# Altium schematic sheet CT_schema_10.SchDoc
size 274 x 160 mm
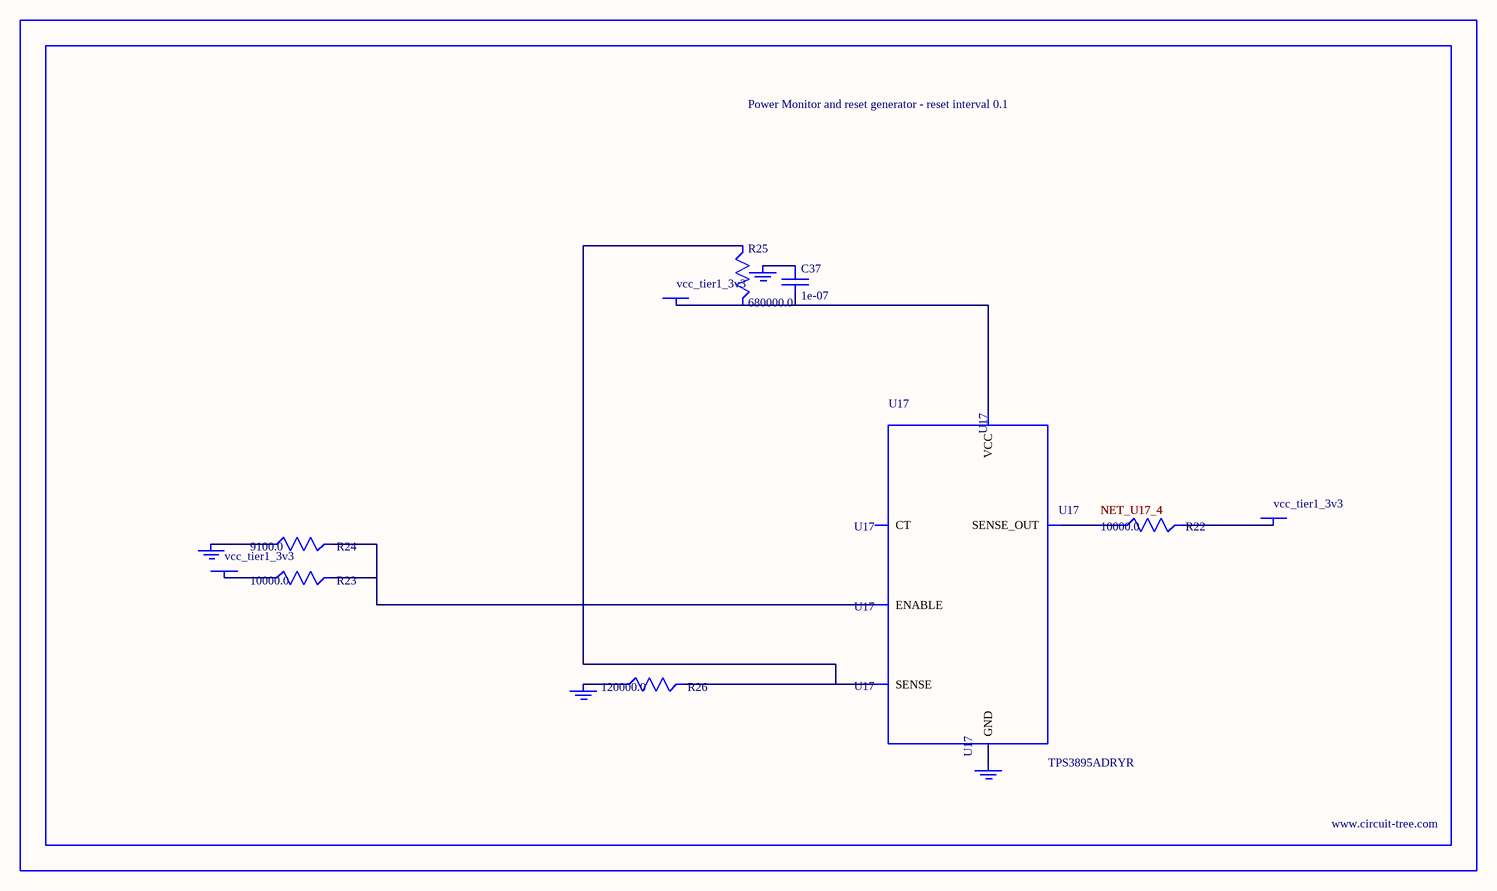
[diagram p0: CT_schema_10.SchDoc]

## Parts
BORDER9  (no value)
C37  1e-07  [C0402]
GND_INSTANCE_9_0  (no value)
GND_INSTANCE_9_1  (no value)
GND_INSTANCE_9_2  (no value)
GND_INSTANCE_9_3  (no value)
POWER_INSTANCE_9_0  vcc_tier1_3v3
POWER_INSTANCE_9_1  vcc_tier1_3v3
POWER_INSTANCE_9_2  vcc_tier1_3v3
R22  10000.0  [R0603]
R23  10000.0  [R0603]
R24  9100.0  [R0603]
R25  680000.0  [R0603]
R26  120000.0  [R0603]
U17  TPS3895ADRYR  [SON-6]

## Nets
NetC37_1: C37.1 GND_INSTANCE_9_2.0(GND)
NetC37_2: C37.2 POWER_INSTANCE_9_2.0(PWR) R25.2 U17.6(VCC)
NetGND_INSTANCE_9_0_0: GND_INSTANCE_9_0.0(GND) R24.1
NetGND_INSTANCE_9_1_0: GND_INSTANCE_9_1.0(GND) R26.1
NetGND_INSTANCE_9_3_0: GND_INSTANCE_9_3.0(GND) U17.2(GND)
NetPOWER_INSTANCE_9_0_0: POWER_INSTANCE_9_0.0(PWR) R23.1
NetPOWER_INSTANCE_9_1_0: POWER_INSTANCE_9_1.0(PWR) R22.2
NetR22_1: R22.1 U17.4(SENSE_OUT)
NetR23_2: R23.2 R24.2 U17.1(ENABLE)
NetR25_1: R25.1 R26.2 U17.3(SENSE)

Not connected (* = marked no-connect by the designer): U17 5(CT)

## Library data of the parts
BORDER9 = BORDER_PAGE9
C37 = C0402C104K3RACTU
GND_INSTANCE_9_0-GND_INSTANCE_9_3 = GND
POWER_INSTANCE_9_0-POWER_INSTANCE_9_2 = PWR
R22 R23 = RC0603JR-0710KL
R24 = RC0603JR-079K1L
R25 = RC0603JR-07680KL
R26 = RC0603JR-07120KL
